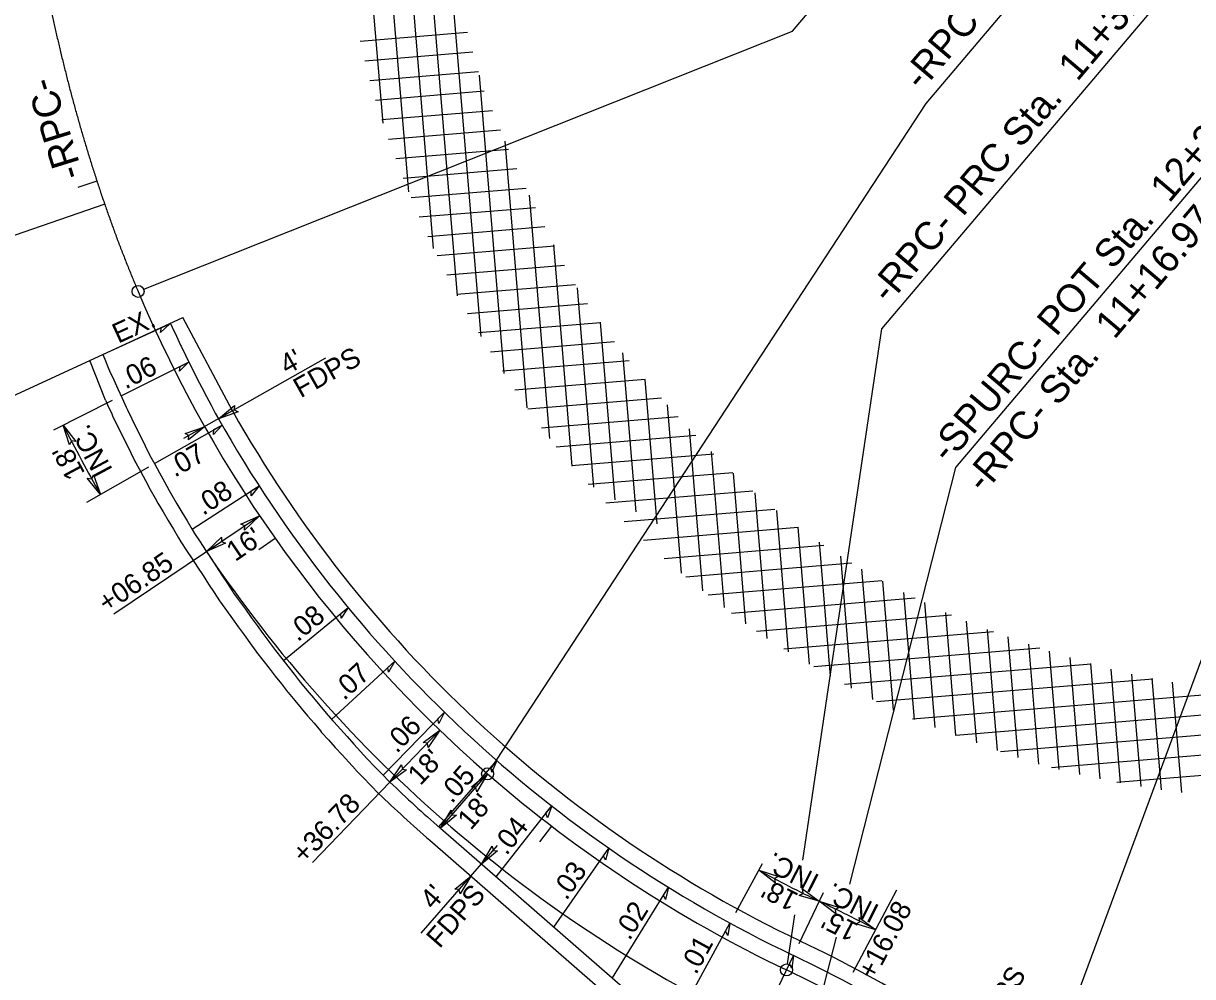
# Model space of a CAD drawing. Extents: x 1761082 to 1764358, y 421907 to 425434.
# Drawn here: x 1761873.7 to 1762165.7, y 423108 to 423346 of the extents above; entities that cross this region are included whole.
import ezdxf

# ---------------------------------------------------------------- set-up
doc = ezdxf.new("R2010")
doc.units = 0
for name, color, linetype in [('MARK HOOKS CENTER STRAIGHT LEFT TURN ARROW CELL', 7, 'Continuous'), ('MARK HOOKS STRAIGHT RIGHT TURN ARROW CELL', 7, 'Continuous'), ('MARK STRAIGHT RIGHT ARROW CELL', 7, 'Continuous'), ('MARK UTURN ARROW CELL', 7, 'Continuous'), ('Prop Conc 4in Sidewalk', 7, 'Continuous'), ('Prop Mkg 3ft Min Skp 3ft Wide White', 7, 'Continuous'), ('Prop Mkg Min Skp 6ft Yellow', 7, 'Continuous'), ('Prop Mkg Skp Wht', 7, 'Continuous'), ('Prop Mkg Solid White Stop Bar', 7, 'Continuous'), ('Prop Mkg Solid Yel Skip LT', 7, 'Continuous'), ('Prop Mkg Solid Yel Skip RT', 7, 'Continuous'), ('Prop Mkg Solid Yellow Edge Line', 7, 'Continuous'), ('Prop Mkg Solid Yellow Lane Line', 7, 'Continuous'), ('Scratch_Level_5', 7, 'Continuous')]:
    doc.layers.add(name, color=color, linetype=linetype)

msp = doc.modelspace()

# ---------------------------------------------------------------- linework, layer by layer
at = {"layer": 'MARK HOOKS CENTER STRAIGHT LEFT TURN ARROW CELL'}
for p, q in [((1761892.07, 423306.57), (1761887.32, 423305.02)), ((1761936.57, 423217.43), (1761932.48, 423214.55)), ((1762005.59, 423145.6), (1762002.55, 423141.63))]:
    msp.add_line(p, q, dxfattribs=at)
at = {"layer": 'MARK STRAIGHT RIGHT ARROW CELL'}
for centre, radius, start, end in [((1762206.3, 423407.55), 330, 202.9084, 228.9609), ((1762206.3, 423407.55), 330, 228.9609, 244.5046), ((1761913.61, 422793.76), 350, 52.7609, 64.5046)]:
    msp.add_arc(centre, radius, start, end, dxfattribs=at)
msp.add_spline([(1761864.22, 423504.65), (1761864.38, 423501.55), (1761864.54, 423498.45), (1761864.7, 423495.34), (1761864.86, 423492.24), (1761865.02, 423489.13), (1761865.19, 423486.03), (1761865.36, 423482.93), (1761865.53, 423479.82), (1761865.7, 423476.72), (1761865.88, 423473.62), (1761866.06, 423470.51), (1761866.25, 423467.41), (1761866.44, 423464.31), (1761866.63, 423461.21), (1761866.83, 423458.11), (1761867.04, 423455.01), (1761867.25, 423451.9), (1761867.47, 423448.8), (1761867.7, 423445.7), (1761867.94, 423442.61), (1761868.18, 423439.51), (1761868.43, 423436.41), (1761868.69, 423433.31), (1761868.96, 423430.21), (1761869.23, 423427.12), (1761869.52, 423424.02), (1761869.82, 423420.93), (1761870.13, 423417.84), (1761870.45, 423414.75), (1761870.78, 423411.66), (1761871.12, 423408.57), (1761871.48, 423405.48), (1761871.85, 423402.39), (1761872.23, 423399.31), (1761872.62, 423396.22), (1761873.03, 423393.14), (1761873.45, 423390.06), (1761873.89, 423386.99), (1761874.34, 423383.91), (1761874.8, 423380.84), (1761875.29, 423377.77), (1761875.78, 423374.7), (1761876.3, 423371.64), (1761876.83, 423368.57), (1761877.38, 423365.51), (1761877.94, 423362.46), (1761878.53, 423359.4), (1761879.13, 423356.36), (1761879.75, 423353.31), (1761880.39, 423350.27), (1761881.05, 423347.23), (1761881.73, 423344.2), (1761882.43, 423341.17), (1761883.15, 423338.15), (1761883.89, 423335.13), (1761884.65, 423332.11), (1761885.43, 423329.11), (1761886.23, 423326.1), (1761887.06, 423323.11), (1761887.91, 423320.12), (1761888.78, 423317.13), (1761889.68, 423314.16), (1761890.59, 423311.19), (1761891.54, 423308.23), (1761892.5, 423305.27), (1761893.49, 423302.33), (1761894.51, 423299.39), (1761895.55, 423296.46), (1761896.61, 423293.54), (1761897.7, 423290.63), (1761898.82, 423287.73), (1761899.97, 423284.84), (1761901.13, 423281.96), (1761902.33, 423279.09)], degree=3, dxfattribs=at)
at = {"layer": 'MARK UTURN ARROW CELL'}
for points in [[(1761903.73, 423279.64), (1762065.78, 423344.06), (1762142.71, 423434.87)], [(1761990.46, 423159.89), (1762099.14, 423325.98), (1762179.84, 423421.24)], [(1762068.33, 423137.05), (1762088.04, 423269.71), (1762168.4, 423364.56)], [(1762080.08, 423131.09), (1762106.58, 423235.12), (1762199.69, 423345.03)], [(1762125.93, 423073.81), (1762189.69, 423246.02), (1762273.94, 423345.46)], [(1761893.99, 423300.89), (1761686.81, 423229.3), (1761608.12, 423136.4)], [(1761906.64, 423269.34), (1761701.33, 423174.65), (1761620.67, 423079.45)], [(1762064.48, 423111.17), (1762066.31, 423123.47)], [(1762069.77, 423090.65), (1762076.71, 423117.86)]]:
    msp.add_lwpolyline(points, dxfattribs=at)
for centre in [(1761902.33, 423279.09), (1761989.63, 423158.64), (1762064.26, 423109.68)]:
    msp.add_circle(centre, 1.5, dxfattribs=at)
at = {"layer": 'Prop Conc 4in Sidewalk'}
for p, q in [((1761987.97, 423267.82), (1761969.83, 423487.08)), ((1761982.11, 423278.01), (1761965.67, 423476.75)), ((1761976.12, 423289.83), (1761961.64, 423464.83)), ((1761969.93, 423303.93), (1761957.85, 423449.9)), ((1761963.5, 423321.09), (1761954.36, 423431.52)), ((1761957.78, 423341.6), (1761984.63, 423343.83)), ((1761958.92, 423336.68), (1761985.95, 423338.92)), ((1761960.2, 423331.77), (1761987.31, 423334.01)), ((1761993.75, 423258.62), (1761987.59, 423333.08)), ((1761961.61, 423326.87), (1761988.75, 423329.12)), ((1761963.18, 423321.98), (1761990.82, 423324.27)), ((1761964.9, 423317.11), (1761992.8, 423319.42)), ((1761999.48, 423250.01), (1761993.97, 423316.62)), ((1761966.69, 423312.24), (1761994.84, 423314.57)), ((1761968.55, 423307.38), (1761996.96, 423309.73)), ((1761970.5, 423302.52), (1761999.25, 423304.9)), ((1762005.13, 423242.4), (1762000.1, 423303.11)), ((1761972.55, 423297.67), (1762001.57, 423300.07)), ((1761974.71, 423292.83), (1762003.9, 423295.25)), ((1761977, 423288.01), (1762006.29, 423290.43)), ((1762010.72, 423235.47), (1762006.15, 423290.71)), ((1761979.4, 423283.19), (1762008.85, 423285.63)), ((1761981.91, 423278.38), (1762011.54, 423280.83)), ((1762016.17, 423230.17), (1762012.05, 423279.99)), ((1761984.56, 423273.58), (1762014.56, 423276.06)), ((1761987.37, 423268.8), (1762017.84, 423271.32)), ((1762021.45, 423227.06), (1762017.78, 423271.4)), ((1761990.32, 423264.02), (1762021.3, 423266.59)), ((1762026.71, 423224.03), (1762023.42, 423263.79)), ((1761993.34, 423259.26), (1762024.96, 423261.87)), ((1761996.43, 423254.5), (1762028.94, 423257.18)), ((1762031.98, 423221.08), (1762028.99, 423257.12)), ((1761999.66, 423249.75), (1762033.02, 423252.51)), ((1762038.01, 423208.77), (1762034.53, 423250.79)), ((1762003.12, 423245.01), (1762037.23, 423247.84)), ((1762006.74, 423240.3), (1762041.58, 423243.18)), ((1762043.39, 423204.36), (1762040.05, 423244.81)), ((1762010.61, 423235.6), (1762046.12, 423238.54)), ((1762048.76, 423200.14), (1762045.53, 423239.12)), ((1762014.77, 423230.93), (1762050.82, 423233.91)), ((1762054.11, 423196.13), (1762051, 423233.74)), ((1762019.15, 423226.27), (1762055.83, 423229.31)), ((1762059.43, 423192.43), (1762056.42, 423228.8)), ((1762023.75, 423221.64), (1762061.31, 423224.74)), ((1762064.72, 423189.14), (1762061.81, 423224.35)), ((1762028.58, 423217.02), (1762067.18, 423220.21)), ((1762070, 423186.03), (1762067.17, 423220.22)), ((1762075.26, 423183), (1762072.49, 423216.46)), ((1762033.71, 423212.43), (1762073.58, 423215.72)), ((1762039.11, 423207.86), (1762080.54, 423211.28)), ((1762080.52, 423180.05), (1762077.8, 423212.98)), ((1762085.78, 423177.21), (1762083.08, 423209.76)), ((1762044.73, 423203.3), (1762088.04, 423206.89)), ((1762091.02, 423174.52), (1762088.35, 423206.71)), ((1762050.55, 423198.77), (1762096.38, 423202.56)), ((1762096.23, 423172.2), (1762093.6, 423203.92)), ((1762101.41, 423170.19), (1762098.83, 423201.38)), ((1762106.59, 423168.25), (1762104.05, 423198.93)), ((1762056.74, 423194.26), (1762105.5, 423198.3)), ((1762111.76, 423166.34), (1762109.24, 423196.75)), ((1762063.6, 423189.81), (1762115.96, 423194.15)), ((1762116.93, 423164.47), (1762114.43, 423194.71)), ((1762122.1, 423162.69), (1762119.6, 423192.82)), ((1762071.05, 423185.41), (1762127.49, 423190.08)), ((1762127.25, 423161.09), (1762124.77, 423191)), ((1762132.38, 423159.72), (1762129.93, 423189.28)), ((1762137.5, 423158.5), (1762135.08, 423187.69)), ((1762078.76, 423181.03), (1762140.35, 423186.13)), ((1762142.6, 423157.39), (1762140.22, 423186.17)), ((1762147.7, 423156.39), (1762145.36, 423184.75)), ((1762086.77, 423176.68), (1762155.78, 423182.39)), ((1762106.52, 423168.28), (1762279.5, 423182.59)), ((1762152.8, 423155.49), (1762150.48, 423183.53)), ((1762157.88, 423154.68), (1762155.58, 423182.47)), ((1762162.96, 423153.96), (1762160.67, 423181.54)), ((1762095.7, 423172.4), (1762179.63, 423179.35)), ((1762117.73, 423164.19), (1762274.62, 423177.17)), ((1762130.44, 423160.22), (1762269.82, 423171.76)), ((1762146.78, 423156.56), (1762267.55, 423166.55))]:
    msp.add_line(p, q, dxfattribs=at)
at = {"layer": 'Prop Mkg 3ft Min Skp 3ft Wide White'}
for centre, radius, start, end in [((1762206.3, 423407.55), 330, 202.9084, 228.9609), ((1762206.3, 423407.55), 330, 228.9609, 244.5046), ((1761913.61, 422793.76), 350, 52.7609, 64.5046)]:
    msp.add_arc(centre, radius, start, end, dxfattribs=at)
msp.add_spline([(1761864.22, 423504.64), (1761864.38, 423501.54), (1761864.54, 423498.44), (1761864.7, 423495.33), (1761864.86, 423492.23), (1761865.02, 423489.13), (1761865.19, 423486.02), (1761865.36, 423482.92), (1761865.53, 423479.81), (1761865.7, 423476.71), (1761865.88, 423473.61), (1761866.06, 423470.51), (1761866.25, 423467.4), (1761866.44, 423464.3), (1761866.63, 423461.2), (1761866.83, 423458.1), (1761867.04, 423455), (1761867.25, 423451.9), (1761867.47, 423448.8), (1761867.7, 423445.7), (1761867.94, 423442.6), (1761868.18, 423439.5), (1761868.43, 423436.4), (1761868.69, 423433.3), (1761868.96, 423430.21), (1761869.23, 423427.11), (1761869.52, 423424.02), (1761869.82, 423420.92), (1761870.13, 423417.83), (1761870.45, 423414.74), (1761870.78, 423411.65), (1761871.12, 423408.56), (1761871.48, 423405.47), (1761871.85, 423402.39), (1761872.23, 423399.3), (1761872.62, 423396.22), (1761873.03, 423393.14), (1761873.45, 423390.06), (1761873.89, 423386.98), (1761874.34, 423383.91), (1761874.8, 423380.83), (1761875.29, 423377.76), (1761875.78, 423374.7), (1761876.3, 423371.63), (1761876.83, 423368.57), (1761877.38, 423365.51), (1761877.94, 423362.45), (1761878.53, 423359.4), (1761879.13, 423356.35), (1761879.75, 423353.31), (1761880.39, 423350.26), (1761881.05, 423347.23), (1761881.73, 423344.19), (1761882.43, 423341.17), (1761883.15, 423338.14), (1761883.89, 423335.12), (1761884.65, 423332.11), (1761885.43, 423329.1), (1761886.23, 423326.1), (1761887.06, 423323.1), (1761887.91, 423320.11), (1761888.78, 423317.13), (1761889.68, 423314.16), (1761890.59, 423311.19), (1761891.54, 423308.22), (1761892.5, 423305.27), (1761893.49, 423302.32), (1761894.51, 423299.39), (1761895.55, 423296.46), (1761896.61, 423293.54), (1761897.7, 423290.63), (1761898.82, 423287.73), (1761899.97, 423284.84), (1761901.13, 423281.96), (1761902.33, 423279.09)], degree=3, dxfattribs=at)
at = {"layer": 'Prop Mkg Skp Wht'}
for p, q in [((1761890.28, 423261.8), (1761913.55, 423272.53)), ((1761977.82, 423145.06), (1762083.3, 423053.24))]:
    msp.add_line(p, q, dxfattribs=at)
for points in [[(1761910.44, 423271.1), (1761910.86, 423270.19), (1761911.9, 423267.92), (1761912.95, 423265.66), (1761913.08, 423265.38), (1761914.19, 423263.14), (1761915.29, 423260.9), (1761916.4, 423258.66), (1761917.08, 423257.28), (1761918.25, 423255.07), (1761919.42, 423252.86), (1761920.59, 423250.66), (1761921.62, 423248.7), (1761922.42, 423247.28)], [(1761893.56, 423263.31), (1761894.02, 423262.18), (1761894.97, 423259.87), (1761895.23, 423259.26), (1761896.26, 423256.99), (1761897.3, 423254.72), (1761898.34, 423252.45), (1761899.38, 423250.18), (1761899.68, 423249.52), (1761900.79, 423247.28), (1761901.89, 423245.04), (1761902.99, 423242.8), (1761904.1, 423240.56), (1761905.2, 423238.32), (1761905.29, 423238.14), (1761906.49, 423235.95), (1761907.7, 423233.76), (1761908.9, 423231.57), (1761910.1, 423229.38), (1761910.74, 423228.22), (1761912.02, 423226.08), (1761913.3, 423223.93), (1761914.58, 423221.79), (1761915.86, 423219.65), (1761916.45, 423218.67), (1761917.81, 423216.58), (1761919.18, 423214.49), (1761920.55, 423212.4), (1761921.91, 423210.31), (1761923.28, 423208.22), (1761924.65, 423206.13), (1761926.01, 423204.04), (1761926.19, 423203.77), (1761927.65, 423201.75), (1761929.12, 423199.73), (1761930.58, 423197.71), (1761932.05, 423195.68), (1761933.51, 423193.66), (1761934.97, 423191.64), (1761935.14, 423191.41), (1761936.68, 423189.44), (1761938.21, 423187.47), (1761939.75, 423185.5), (1761941.29, 423183.53), (1761942.82, 423181.56), (1761942.9, 423181.46), (1761944.51, 423179.55), (1761946.12, 423177.64), (1761947.73, 423175.73), (1761949.34, 423173.82), (1761950.95, 423171.91), (1761951.19, 423171.63), (1761952.87, 423169.77), (1761954.55, 423167.92), (1761956.22, 423166.07), (1761957.9, 423164.22), (1761959.58, 423162.37), (1761959.65, 423162.3), (1761961.39, 423160.51), (1761963.14, 423158.72), (1761965.23, 423156.57)]]:
    msp.add_lwpolyline(points, dxfattribs=at)
for centre, radius, start, end in [((1762206.3, 423407.55), 326, 209.4472, 244.5046), ((1762206.3, 423407.55), 348, 226.1523, 228.9609), ((1761913.61, 422793.76), 354, 52.7609, 64.5046)]:
    msp.add_arc(centre, radius, start, end, dxfattribs=at)
at = {"layer": 'Prop Mkg Solid White Stop Bar'}
for p, q in [((1761925.9, 423249.24), (1761913.55, 423272.53)), ((1761894.17, 423251.95), (1761890.28, 423261.8)), ((1761975.19, 423142.05), (1762070.45, 423059.13))]:
    msp.add_line(p, q, dxfattribs=at)
msp.add_lwpolyline([(1761894.17, 423251.95), (1761894.7, 423250.79), (1761895.74, 423248.52), (1761896.07, 423247.8), (1761897.2, 423245.51), (1761898.3, 423243.27), (1761899.41, 423241.03), (1761900.51, 423238.79), (1761901.61, 423236.55), (1761901.74, 423236.29), (1761902.99, 423234.02), (1761904.19, 423231.84), (1761905.39, 423229.65), (1761906.59, 423227.46), (1761907.27, 423226.23), (1761908.58, 423224.02), (1761909.87, 423221.88), (1761911.15, 423219.74), (1761912.43, 423217.59), (1761913.05, 423216.55), (1761914.46, 423214.39), (1761915.83, 423212.3), (1761917.2, 423210.21), (1761918.56, 423208.12), (1761919.93, 423206.03), (1761921.3, 423203.94), (1761922.66, 423201.85), (1761922.89, 423201.5), (1761924.41, 423199.4), (1761925.88, 423197.38), (1761927.34, 423195.36), (1761928.81, 423193.34), (1761930.27, 423191.31), (1761931.74, 423189.29), (1761931.94, 423189.01), (1761933.52, 423186.98), (1761935.06, 423185.01), (1761936.6, 423183.04), (1761938.13, 423181.07), (1761939.67, 423179.1), (1761939.79, 423178.94), (1761941.45, 423176.98), (1761943.06, 423175.07), (1761944.67, 423173.16), (1761946.28, 423171.25), (1761947.89, 423169.34), (1761948.18, 423168.99), (1761949.91, 423167.09), (1761951.58, 423165.24), (1761953.26, 423163.39), (1761954.94, 423161.54), (1761956.62, 423159.69), (1761956.73, 423159.56), (1761958.53, 423157.72), (1761962.41, 423153.74)], dxfattribs=at)
for centre, radius, start, end in [((1762206.3, 423407.55), 322, 209.4472, 244.5046), ((1762206.3, 423407.55), 352, 226.1415, 228.9609), ((1761913.61, 422793.76), 358, 52.7609, 64.5046)]:
    msp.add_arc(centre, radius, start, end, dxfattribs=at)
at = {"layer": 'Prop Mkg Solid Yel Skip RT'}
for p, q in [((1761949.17, 423262.38), (1761913.71, 423242.36)), ((1761881.3, 423244.56), (1761895.97, 423251.91)), ((1761889.54, 423226.44), (1761905.06, 423235.3)), ((1761896.31, 423198.55), (1761932.68, 423223.07)), ((1761965.23, 423156.57), (1761977.7, 423169.56)), ((1761977.82, 423145.06), (1761989.63, 423158.64)), ((1761945.92, 423136.47), (1761965.23, 423156.57)), ((1761973.06, 423118.87), (1761992.08, 423140.71)), ((1762051.6, 423124.05), (1762058.28, 423136.29)), ((1762067.41, 423116.29), (1762073.49, 423129.04)), ((1762080.95, 423109.13), (1762091.83, 423129.65))]:
    msp.add_line(p, q, dxfattribs=at)
for centre, radius, start, end in [((1762206.3, 423407.55), 360.97, 206.634, 209.7593), ((1762206.3, 423407.55), 310.98, 241.3796, 244.5046), ((1761913.61, 422793.76), 369.02, 62.0488, 64.5046)]:
    msp.add_arc(centre, radius, start, end, dxfattribs=at)
at = {"layer": 'Prop Mkg Solid Yellow Edge Line'}
msp.add_arc((1762206.3, 423407.55), 346, 213.9873, 244.5046, dxfattribs=at)
at = {"layer": 'Prop Mkg Solid Yellow Lane Line'}
for points in [[(1761927.3, 423249.02), (1761922.42, 423247.28), (1761926.44, 423250.59), (1761926.32, 423249.48)], [(1761885.2, 423240.79), (1761883.63, 423245.73), (1761886.8, 423241.59), (1761885.7, 423241.75)], [(1761914.06, 423243.57), (1761918.94, 423245.31), (1761914.91, 423242), (1761915.04, 423243.11)], [(1761891.23, 423233.26), (1761892.94, 423228.37), (1761889.66, 423232.42), (1761890.77, 423232.29)], [(1761927.96, 423220.95), (1761932.68, 423223.07), (1761928.93, 423219.45), (1761928.97, 423220.57)], [(1761924.14, 423216.25), (1761919.41, 423214.13), (1761923.16, 423217.75), (1761923.13, 423216.63)], [(1761973.53, 423166.48), (1761977.7, 423169.56), (1761974.8, 423165.23), (1761974.6, 423166.32)], [(1761969.4, 423159.65), (1761965.23, 423156.57), (1761968.13, 423160.9), (1761968.33, 423159.8)], [(1761985.62, 423155.37), (1761989.63, 423158.64), (1761986.95, 423154.17), (1761986.69, 423155.26)], [(1761981.83, 423148.33), (1761977.82, 423145.06), (1761980.5, 423149.53), (1761980.76, 423148.44)], [(1761992.1, 423139.4), (1761988.08, 423136.12), (1761990.77, 423140.59), (1761991.03, 423139.5)], [(1762061.44, 423131.4), (1762057.34, 423134.56), (1762062.3, 423132.97), (1762061.3, 423132.47)], [(1761981.44, 423129.83), (1761985.46, 423133.11), (1761982.77, 423128.64), (1761982.52, 423129.73)], [(1762068.26, 423129.89), (1762072.44, 423126.85), (1762067.44, 423128.3), (1762068.43, 423128.83)], [(1762076.56, 423123.71), (1762072.44, 423126.85), (1762077.41, 423125.28), (1762076.42, 423124.78)], [(1762082.37, 423122.76), (1762086.57, 423119.73), (1762081.56, 423121.16), (1762082.54, 423121.69)]]:
    msp.add_lwpolyline(points, close=True, dxfattribs=at)
at = {"layer": 'Scratch_Level_5'}
for p, q in [((1761893.56, 423263.31), (1761910.27, 423271.02)), ((1761898.1, 423252.98), (1761914.9, 423261.4)), ((1761906.42, 423236.08), (1761923.3, 423245.73)), ((1761915.81, 423219.73), (1761932.54, 423230.55)), ((1761938.66, 423186.9), (1761954.76, 423200.17)), ((1761950.67, 423172.24), (1761966.44, 423186.77)), ((1761963.54, 423158.31), (1761978.84, 423174.02)), ((1761977.44, 423145.39), (1761991.91, 423161.96)), ((1761991.77, 423132.92), (1762005.62, 423150.64)), ((1762006.18, 423120.37), (1762019.92, 423140.08)), ((1762020.77, 423107.67), (1762034.78, 423130.32)), ((1762035.62, 423094.75), (1762050.15, 423121.38)), ((1762050.82, 423081.51), (1762065.98, 423113.29))]:
    msp.add_line(p, q, dxfattribs=at)
for points in [[(1761910.27, 423271.02), (1761907.96, 423268.85), (1761908.17, 423270.05)], [(1761914.9, 423261.4), (1761912.66, 423259.16), (1761912.83, 423260.37)], [(1761923.3, 423245.73), (1761921.19, 423243.38), (1761921.29, 423244.59)], [(1761932.54, 423230.55), (1761930.56, 423228.08), (1761930.6, 423229.29)], [(1761954.76, 423200.17), (1761953.09, 423197.49), (1761952.98, 423198.7)], [(1761966.44, 423186.77), (1761964.91, 423184), (1761964.74, 423185.2)], [(1761978.84, 423174.02), (1761977.46, 423171.17), (1761977.22, 423172.36)], [(1761991.91, 423161.96), (1761990.69, 423159.05), (1761990.39, 423160.22)], [(1762005.62, 423150.64), (1762004.56, 423147.66), (1762004.19, 423148.82)], [(1762019.92, 423140.08), (1762019.03, 423137.05), (1762018.6, 423138.18)], [(1762034.78, 423130.32), (1762034.05, 423127.24), (1762033.56, 423128.35)], [(1762050.15, 423121.38), (1762049.59, 423118.27), (1762049.04, 423119.35)], [(1762065.98, 423113.29), (1762065.59, 423110.15), (1762064.99, 423111.2)]]:
    msp.add_lwpolyline(points, close=True, dxfattribs=at)

# ---------------------------------------------------------------- texts
at = {"layer": 'MARK HOOKS STRAIGHT RIGHT TURN ARROW CELL'}
msp.add_text('-RPC-', height=7, rotation=107.2423, dxfattribs=at).set_placement((1761888.7, 423308.15))
at = {"layer": 'MARK UTURN ARROW CELL'}
for s, p in [('-RPC- PCC Sta.  12+20.61', (1762098, 423328.93)), ('-RPC- PRC Sta.  11+31.08', (1762089.82, 423275.72)), ('-SPURC- POT Sta.  12+20.98=', (1762104.71, 423235.86)), ("-RPC- Sta.  11+16.97,   16' LT", (1762113.53, 423228.39))]:
    msp.add_text(s, height=7, rotation=49.7301, dxfattribs=at).set_placement(p)
at = {"layer": 'Prop Mkg Min Skp 6ft Yellow'}
for s, rotation, p in [('EX.', 24.7589, (1761897.38, 423266)), ('.06', 26.6335, (1761899.2, 423254.59)), ('INC.', 118.1966, (1761896.13, 423234.54)), ("18' ", 118.1966, (1761889.19, 423233.72)), ('.07', 29.7593, (1761911.5, 423232.54)), ('.08', 32.8845, (1761918.58, 423223.01)), ('.08', 39.503, (1761942.21, 423191.44)), ('.07', 42.6282, (1761953.79, 423176.81)), ('.06', 45.7535, (1761966.92, 423163.57)), ('.05', 48.8787, (1761980.69, 423151.01)), ('.04', 52.0039, (1761994.34, 423138.07)), ('INC.', 152.9421, (1762072.82, 423133.19)), ('.03', 55.1291, (1762009.31, 423126.86)), ("18'", 152.9421, (1762067.59, 423128.56)), ('INC.', 153.2767, (1762087.77, 423125.64)), ('.02', 58.2544, (1762025.08, 423116.82)), ("15'", 153.2767, (1762082.56, 423120.98)), ('.01', 61.3796, (1762041.67, 423108.29))]:
    msp.add_text(s, height=5, rotation=rotation, dxfattribs=at).set_placement(p)
at = {"layer": 'Prop Mkg Solid Yel Skip LT'}
for s, rotation, p in [("4'", 29.4472, (1761939.54, 423258.19)), ('FDPS', 29.4472, (1761942.95, 423252.37)), ("16'", 33.9873, (1761926.58, 423211.5)), ('+06.85', 33.9873, (1761894.51, 423198.69)), ("18'", 46.1523, (1761972.79, 423155.51)), ('+36.78', 46.1523, (1761943.89, 423135.94)), ("18'", 48.9609, (1761985.42, 423144.37)), ("4'", 48.9609, (1761976.08, 423124.47)), ('FDPS', 48.9609, (1761977.65, 423114.83)), ('+16.08', 62.0488, (1762086.1, 423106.9)), ('FDPS', 57.1378, (1762114.61, 423093.49))]:
    msp.add_text(s, height=5, rotation=rotation, dxfattribs=at).set_placement(p)

doc.saveas('drawing.dxf')
